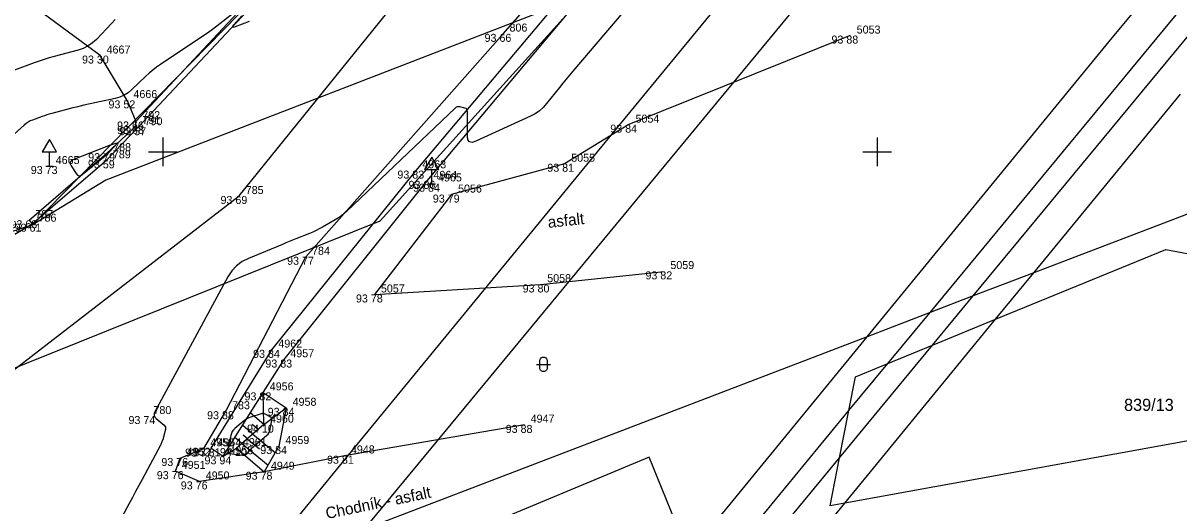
# Model space of a CAD drawing. Extents: x -711081 to -709338, y -1025122 to -1024092.
# Drawn here: x -709804.89 to -709764.45, y -1024537.41 to -1024520.49 of the extents above; entities that cross this region are included whole.
import ezdxf

# ---------------------------------------------------------------- set-up
doc = ezdxf.new("R2010")
doc.units = 0
for name, color, linetype in [('Ex_Major Contours', 7, 'Continuous'), ('Ex_Minor Contours', 7, 'Continuous'), ('Z_body', 7, 'Continuous'), ('Z_body_cisla', 7, 'Continuous'), ('Z_body_vysky_redukovane', 7, 'Continuous'), ('Z_cesta', 7, 'Continuous'), ('Z_dopravni_znacky', 7, 'Continuous'), ('Z_hektometricka_sit', 7, 'Continuous'), ('Z_hrany_paty', 7, 'Continuous'), ('Z_katastr_cisla_pozemkova', 7, 'Continuous'), ('Z_katastr_hranice', 7, 'Continuous'), ('Z_katastr_vnitrni_kresba', 7, 'Continuous'), ('Z_komunikace', 7, 'Continuous'), ('Z_komunikace_osa', 7, 'Continuous'), ('Z_obruba', 7, 'Continuous'), ('Z_popisy', 7, 'Continuous'), ('Z_rozhranni', 7, 'Continuous'), ('Z_svodidlo_betonove', 7, 'Continuous'), ('Z_technicke_srafy', 7, 'Continuous'), ('Z_znaky_kultur', 7, 'Continuous')]:
    doc.layers.add(name, color=color, linetype=linetype)

# ---------------------------------------------------------------- blocks, each defined once
blk = doc.blocks.new('POINT_DISPLAY')
blk.add_line((0, 0), (0, 0))
blk = doc.blocks.new('Z527')
for p, q in [((0, 0.93), (-0.25, 0.5)), ((0.25, 0.5), (0, 0.93)), ((-0.25, 0.5), (0.25, 0.5)), ((0, 0), (0, 0.5)), ((-0.13, 0), (0.13, 0))]:
    blk.add_line(p, q)
blk = doc.blocks.new('Z316')
for p, q in [((-0.25, 0), (0.25, 0)), ((-0.13, 0.15), (-0.1, 0.2)), ((-0.13, -0.15), (-0.13, 0.15)), ((-0.1, 0.2), (-0.08, 0.23)), ((-0.08, 0.23), (-0.03, 0.25)), ((-0.03, 0.25), (0.03, 0.25)), ((0.03, 0.25), (0.08, 0.23)), ((0.08, 0.23), (0.1, 0.2)), ((0.1, 0.2), (0.13, 0.15)), ((0.13, 0.15), (0.13, -0.15)), ((-0.1, -0.2), (-0.13, -0.15)), ((-0.08, -0.23), (-0.1, -0.2)), ((-0.03, -0.25), (-0.08, -0.23)), ((0.03, -0.25), (-0.03, -0.25)), ((0.08, -0.23), (0.03, -0.25)), ((0.1, -0.2), (0.08, -0.23)), ((0.13, -0.15), (0.1, -0.2))]:
    blk.add_line(p, q)

msp = doc.modelspace()

# ---------------------------------------------------------------- linework, layer by layer
at = {"layer": 'Ex_Major Contours'}
msp.add_lwpolyline([(-709797.721, -1024535.362), (-709797.724, -1024535.384), (-709797.724, -1024535.406), (-709797.724, -1024535.428), (-709797.717, -1024535.517), (-709797.713, -1024535.537), (-709797.704, -1024535.552), (-709797.689, -1024535.562), (-709797.67, -1024535.567), (-709797.214, -1024535.627), (-709797.167, -1024535.628), (-709797.124, -1024535.618), (-709797.086, -1024535.598), (-709797.05, -1024535.568), (-709796.917, -1024535.425), (-709796.884, -1024535.389), (-709796.849, -1024535.355), (-709796.813, -1024535.322), (-709796.777, -1024535.289), (-709796.366, -1024534.934), (-709796.32, -1024534.889), (-709796.285, -1024534.838), (-709796.258, -1024534.781), (-709796.241, -1024534.72), (-709796.183, -1024534.421), (-709796.181, -1024534.38), (-709796.19, -1024534.344), (-709796.211, -1024534.314), (-709796.244, -1024534.289), (-709796.399, -1024534.201), (-709796.439, -1024534.183), (-709796.479, -1024534.174), (-709796.52, -1024534.174), (-709796.562, -1024534.184), (-709796.925, -1024534.299), (-709796.998, -1024534.326), (-709797.067, -1024534.36), (-709797.132, -1024534.401), (-709797.193, -1024534.449), (-709797.478, -1024534.695), (-709797.53, -1024534.747), (-709797.572, -1024534.806), (-709797.604, -1024534.87), (-709797.626, -1024534.941), (-709797.717, -1024535.34)], close=True, dxfattribs=at)
at = {"layer": 'Ex_Minor Contours'}
for points in [[(-709782.085, -1024517.973), (-709785.654, -1024522.182), (-709785.772, -1024522.321), (-709785.888, -1024522.462), (-709786.003, -1024522.603), (-709786.118, -1024522.745), (-709786.573, -1024523.315), (-709786.693, -1024523.449), (-709786.826, -1024523.567), (-709786.972, -1024523.668), (-709787.131, -1024523.752), (-709789.054, -1024524.635), (-709789.18, -1024524.673), (-709789.271, -1024524.655), (-709789.325, -1024524.58), (-709789.342, -1024524.45), (-709789.34, -1024523.589), (-709789.346, -1024523.546), (-709789.363, -1024523.513), (-709789.391, -1024523.488), (-709789.431, -1024523.473), (-709789.614, -1024523.428), (-709789.658, -1024523.422), (-709789.699, -1024523.428), (-709789.737, -1024523.444), (-709789.773, -1024523.471), (-709793.558, -1024527.082), (-709793.653, -1024527.168), (-709793.753, -1024527.248), (-709793.858, -1024527.321), (-709793.967, -1024527.388), (-709794.416, -1024527.645), (-709794.527, -1024527.706), (-709794.64, -1024527.764), (-709794.756, -1024527.817), (-709794.873, -1024527.866), (-709795.346, -1024528.054), (-709795.464, -1024528.101), (-709795.582, -1024528.148), (-709795.7, -1024528.196), (-709795.818, -1024528.245), (-709797.004, -1024528.735), (-709797.227, -1024528.849), (-709797.421, -1024528.995), (-709797.586, -1024529.173), (-709797.722, -1024529.382), (-709800.281, -1024534.114), (-709800.306, -1024534.179), (-709800.307, -1024534.239), (-709800.284, -1024534.295), (-709800.238, -1024534.346), (-709799.96, -1024534.581), (-709799.931, -1024534.612), (-709799.913, -1024534.647), (-709799.906, -1024534.686), (-709799.911, -1024534.729), (-709799.961, -1024534.936), (-709799.968, -1024534.965), (-709799.976, -1024534.995), (-709799.985, -1024535.024), (-709799.995, -1024535.053), (-709800.035, -1024535.168), (-709800.046, -1024535.196), (-709800.057, -1024535.224), (-709800.07, -1024535.252), (-709800.084, -1024535.279), (-709800.728, -1024536.485), (-709800.84, -1024536.695), (-709800.953, -1024536.905), (-709801.065, -1024537.115), (-709801.177, -1024537.325), (-709802.637, -1024540.048)], [(-709797.157, -1024519.858), (-709798.003, -1024520.52), (-709798.158, -1024520.638), (-709798.314, -1024520.754), (-709798.473, -1024520.867), (-709798.634, -1024520.977), (-709800.08, -1024521.943), (-709800.218, -1024522.039), (-709800.351, -1024522.141), (-709800.48, -1024522.249), (-709800.604, -1024522.362), (-709801.092, -1024522.825), (-709801.22, -1024522.931), (-709801.358, -1024523.017), (-709801.506, -1024523.084), (-709801.665, -1024523.13), (-709802.761, -1024523.372), (-709802.892, -1024523.402), (-709803.023, -1024523.433), (-709803.153, -1024523.465), (-709803.282, -1024523.499), (-709803.889, -1024523.661), (-709803.974, -1024523.685), (-709804.059, -1024523.71), (-709804.143, -1024523.738), (-709804.226, -1024523.767), (-709804.558, -1024523.888), (-709804.639, -1024523.922), (-709804.716, -1024523.963), (-709804.788, -1024524.011), (-709804.856, -1024524.067), (-709806.483, -1024525.524)], [(-709796.977, -1024520.436), (-709797.466, -1024520.625), (-709797.529, -1024520.644), (-709797.558, -1024520.639), (-709797.553, -1024520.61), (-709797.513, -1024520.558), (-709797.236, -1024520.243)], [(-709801.665, -1024520.372), (-709801.797, -1024520.51), (-709802.327, -1024521.063), (-709802.466, -1024521.19), (-709802.619, -1024521.295), (-709802.784, -1024521.378), (-709802.962, -1024521.438), (-709803.801, -1024521.662), (-709803.979, -1024521.712), (-709804.155, -1024521.765), (-709804.331, -1024521.823), (-709804.505, -1024521.884), (-709805.198, -1024522.137)]]:
    msp.add_lwpolyline(points, dxfattribs=at)
msp.add_lwpolyline([(-709802.99, -1024525.82), (-709802.939, -1024525.844), (-709802.883, -1024525.838), (-709802.822, -1024525.801), (-709802.019, -1024525.146), (-709801.991, -1024525.123), (-709801.964, -1024525.098), (-709801.937, -1024525.073), (-709801.912, -1024525.046), (-709801.804, -1024524.93), (-709801.783, -1024524.907), (-709801.762, -1024524.885), (-709801.741, -1024524.862), (-709801.72, -1024524.84), (-709801.602, -1024524.715), (-709801.599, -1024524.71), (-709801.599, -1024524.707), (-709801.601, -1024524.706), (-709801.607, -1024524.706), (-709801.635, -1024524.707), (-709801.642, -1024524.708), (-709801.649, -1024524.709), (-709801.656, -1024524.711), (-709801.663, -1024524.713), (-709801.803, -1024524.759), (-709801.829, -1024524.768), (-709801.855, -1024524.777), (-709801.88, -1024524.786), (-709801.905, -1024524.796), (-709803.148, -1024525.289), (-709803.209, -1024525.325), (-709803.24, -1024525.37), (-709803.241, -1024525.424), (-709803.212, -1024525.489), (-709803.037, -1024525.766)], close=True, dxfattribs=at)
at = {"layer": 'Z_cesta'}
for p, q in [((-709802.2, -1024521.63), (-709804.24, -1024520.12)), ((-709801.25, -1024523.2), (-709802.2, -1024521.63)), ((-709801.25, -1024523.2), (-709800.95, -1024523.94))]:
    msp.add_line(p, q, dxfattribs=at)
at = {"layer": 'Z_hektometricka_sit'}
for p, q in [((-709800, -1024524.5), (-709800, -1024525.5)), ((-709775, -1024524.5), (-709775, -1024525.5)), ((-709800.5, -1024525), (-709799.5, -1024525)), ((-709775.5, -1024525), (-709774.5, -1024525))]:
    msp.add_line(p, q, dxfattribs=at)
at = {"layer": 'Z_hrany_paty'}
for p, q in [((-709796.49, -1024533.43), (-709795.68, -1024533.97)), ((-709796.47, -1024534.56), (-709796.49, -1024533.43)), ((-709796.47, -1024534.56), (-709795.68, -1024533.97)), ((-709795.68, -1024533.97), (-709795.94, -1024535.31)), ((-709796.47, -1024534.56), (-709797.42, -1024535.38)), ((-709797.89, -1024535.67), (-709797.42, -1024535.38)), ((-709797.42, -1024535.38), (-709796.45, -1024536.21)), ((-709795.94, -1024535.31), (-709796.45, -1024536.21))]:
    msp.add_line(p, q, dxfattribs=at)
at = {"layer": 'Z_katastr_hranice'}
for p, q in [((-709783.98, -1024524.02), (-709777.86, -1024516.55)), ((-709785.24, -1024519.5), (-709802, -1024526)), ((-709793.08, -1024535.12), (-709783.98, -1024524.02)), ((-709756.45, -1024524.23), (-709769.52, -1024529.24)), ((-709802, -1024526), (-709804.58, -1024527.57)), ((-709804.58, -1024527.57), (-709811.25, -1024529.69)), ((-709770.86, -1024530.87), (-709764.9, -1024528.42)), ((-709764.9, -1024528.42), (-709756.66, -1024530.01)), ((-709769.52, -1024529.24), (-709771.64, -1024530.05)), ((-709771.64, -1024530.05), (-709773.15, -1024530.63)), ((-709773.15, -1024530.63), (-709775.35, -1024531.48)), ((-709773.07, -1024531.78), (-709770.86, -1024530.87)), ((-709775.35, -1024531.48), (-709792.97, -1024538.24)), ((-709774.63, -1024532.42), (-709773.07, -1024531.78)), ((-709775.76, -1024532.89), (-709774.63, -1024532.42)), ((-709775.99, -1024534.07), (-709775.76, -1024532.89)), ((-709776.32, -1024535.72), (-709775.99, -1024534.07)), ((-709760.23, -1024534.42), (-709776.13, -1024537.31)), ((-709795.34, -1024537.87), (-709793.08, -1024535.12)), ((-709782.98, -1024535.7), (-709793.81, -1024540.21)), ((-709781.6, -1024539.11), (-709782.98, -1024535.7)), ((-709776.65, -1024537.4), (-709776.32, -1024535.72)), ((-709776.13, -1024537.31), (-709776.65, -1024537.4))]:
    msp.add_line(p, q, dxfattribs=at)
at = {"layer": 'Z_katastr_vnitrni_kresba'}
for p, q in [((-709766.78, -1024521.01), (-709758.92, -1024511.56)), ((-709773.15, -1024530.63), (-709758.42, -1024512.78)), ((-709771.64, -1024530.05), (-709758.24, -1024513.82)), ((-709773.68, -1024514.87), (-709792.97, -1024538.24)), ((-709804.58, -1024527.57), (-709794.45, -1024517.22)), ((-709792.4, -1024527.42), (-709785.24, -1024519.5)), ((-709775.35, -1024531.48), (-709766.78, -1024521.01)), ((-709769.52, -1024529.24), (-709764.39, -1024522.98)), ((-709829.33, -1024542.31), (-709792.4, -1024527.42)), ((-709770.86, -1024530.87), (-709769.52, -1024529.24)), ((-709773.07, -1024531.78), (-709771.64, -1024530.05)), ((-709774.63, -1024532.42), (-709773.15, -1024530.63)), ((-709776.13, -1024537.31), (-709770.86, -1024530.87)), ((-709781.6, -1024539.11), (-709775.35, -1024531.48)), ((-709776.32, -1024535.72), (-709773.07, -1024531.78)), ((-709775.99, -1024534.07), (-709774.63, -1024532.42)), ((-709781.12, -1024540.29), (-709775.99, -1024534.07)), ((-709780.78, -1024541.13), (-709776.32, -1024535.72)), ((-709780.28, -1024542.38), (-709776.13, -1024537.31))]:
    msp.add_line(p, q, dxfattribs=at)
at = {"layer": 'Z_komunikace'}
for p, q in [((-709788.09, -1024520.87), (-709780.35, -1024512.04)), ((-709800.87, -1024524.14), (-709796.7, -1024519.7)), ((-709795, -1024528.68), (-709788.09, -1024520.87)), ((-709801.97, -1024525.3), (-709800.87, -1024524.14)), ((-709804.58, -1024527.52), (-709801.97, -1024525.3)), ((-709810.36, -1024530.97), (-709804.58, -1024527.52)), ((-709797.8, -1024534.09), (-709795, -1024528.68)), ((-709798.57, -1024535.4), (-709797.8, -1024534.09)), ((-709787.35, -1024534.57), (-709793.65, -1024535.65)), ((-709799.4, -1024535.73), (-709798.57, -1024535.4)), ((-709799.56, -1024536.19), (-709799.4, -1024535.73)), ((-709793.65, -1024535.65), (-709796.45, -1024536.21)), ((-709798.72, -1024536.55), (-709799.56, -1024536.19)), ((-709796.45, -1024536.21), (-709798.72, -1024536.55))]:
    msp.add_line(p, q, dxfattribs=at)
at = {"layer": 'Z_komunikace_osa'}
for p, q in [((-709797.33, -1024526.55), (-709791, -1024518.69)), ((-709807.7, -1024534.56), (-709797.33, -1024526.55))]:
    msp.add_line(p, q, dxfattribs=at)
at = {"layer": 'Z_obruba'}
for p, q in [((-709800.95, -1024523.94), (-709796.84, -1024519.54)), ((-709801.96, -1024525.05), (-709800.95, -1024524.1)), ((-709800.95, -1024524.1), (-709800.95, -1024523.94)), ((-709804.68, -1024527.4), (-709801.96, -1024525.05)), ((-709804.68, -1024527.4), (-709804.58, -1024527.52))]:
    msp.add_line(p, q, dxfattribs=at)
at = {"layer": 'Z_rozhranni'}
for p, q in [((-709775.95, -1024520.93), (-709783.69, -1024524.05)), ((-709783.69, -1024524.05), (-709785.94, -1024525.42)), ((-709785.94, -1024525.42), (-709789.9, -1024526.5)), ((-709789.9, -1024526.5), (-709792.59, -1024530)), ((-709786.78, -1024529.65), (-709782.46, -1024529.19)), ((-709792.59, -1024530), (-709786.78, -1024529.65))]:
    msp.add_line(p, q, dxfattribs=at)
at = {"layer": 'Z_svodidlo_betonove'}
for p, q in [((-709791.14, -1024525.66), (-709780.82, -1024513.38)), ((-709790.75, -1024526.02), (-709780.45, -1024513.72)), ((-709796.19, -1024531.94), (-709791.14, -1024525.66)), ((-709795.76, -1024532.28), (-709790.75, -1024526.02)), ((-709798.31, -1024535.39), (-709796.19, -1024531.94)), ((-709796.49, -1024533.43), (-709795.76, -1024532.28)), ((-709797.89, -1024535.67), (-709796.49, -1024533.43)), ((-709798.31, -1024535.39), (-709797.89, -1024535.67))]:
    msp.add_line(p, q, dxfattribs=at)
at = {"layer": 'Z_technicke_srafy'}
for p, q in [((-709796.47, -1024534.56), (-709796.94, -1024534.15)), ((-709796.85, -1024534.89), (-709797.21, -1024534.58)), ((-709796.66, -1024534.73), (-709796.87, -1024534.55)), ((-709797.24, -1024535.22), (-709797.48, -1024535.01)), ((-709797.24, -1024535.22), (-709796.32, -1024535.98)), ((-709797.04, -1024535.06), (-709797.19, -1024534.93)), ((-709797.05, -1024535.06), (-709796.62, -1024535.41)), ((-709796.85, -1024534.89), (-709796.07, -1024535.54))]:
    msp.add_line(p, q, dxfattribs=at)

# ---------------------------------------------------------------- block references
at = {"layer": 'Z_body'}
for p in [(-709788.09, -1024520.87), (-709775.95, -1024520.93), (-709802.2, -1024521.63), (-709801.25, -1024523.2), (-709800.95, -1024523.94), (-709800.95, -1024524.1), (-709800.87, -1024524.14), (-709783.69, -1024524.05), (-709801.96, -1024525.05), (-709803.97, -1024525.5), (-709801.97, -1024525.3), (-709785.94, -1024525.42), (-709791.14, -1024525.66), (-709790.75, -1024526.02), (-709790.59, -1024526.12), (-709797.33, -1024526.55), (-709789.9, -1024526.5), (-709804.68, -1024527.4), (-709804.58, -1024527.52), (-709795, -1024528.68), (-709782.46, -1024529.19), (-709786.78, -1024529.65), (-709792.59, -1024530), (-709796.19, -1024531.94), (-709795.76, -1024532.28), (-709796.49, -1024533.43), (-709795.68, -1024533.97), (-709800.55, -1024534.26), (-709797.8, -1024534.09), (-709796.47, -1024534.56), (-709787.35, -1024534.57), (-709798.57, -1024535.4), (-709798.31, -1024535.39), (-709797.42, -1024535.38), (-709795.94, -1024535.31), (-709799.4, -1024535.73), (-709797.89, -1024535.67), (-709793.65, -1024535.65), (-709799.56, -1024536.19), (-709796.45, -1024536.21), (-709798.72, -1024536.55)]:
    msp.add_blockref('POINT_DISPLAY', p, dxfattribs=at)
at = {"layer": 'Z_dopravni_znacky'}
for p in [(-709803.97, -1024525.5), (-709790.59, -1024526.12)]:
    msp.add_blockref('Z527', p, dxfattribs=at)
at = {"layer": 'Z_znaky_kultur'}
msp.add_blockref('Z316', (-709786.68, -1024532.45), dxfattribs=at)

# ---------------------------------------------------------------- texts
at = {"layer": 'Z_body_cisla'}
for s, p in [('806', (-709787.87, -1024520.79)), ('5053', (-709775.72, -1024520.86)), ('4667', (-709801.97, -1024521.56)), ('4666', (-709801.03, -1024523.12)), ('792', (-709800.72, -1024523.86)), ('791', (-709800.72, -1024524.03)), ('790', (-709800.64, -1024524.07)), ('5054', (-709783.46, -1024523.98)), ('788', (-709801.74, -1024524.98)), ('789', (-709801.75, -1024525.23)), ('5055', (-709785.71, -1024525.35)), ('4665', (-709803.75, -1024525.43)), ('4963', (-709790.92, -1024525.58)), ('4964', (-709790.53, -1024525.95)), ('4965', (-709790.37, -1024526.04)), ('785', (-709797.1, -1024526.48)), ('5056', (-709789.67, -1024526.43)), ('787', (-709804.46, -1024527.32)), ('786', (-709804.35, -1024527.45)), ('784', (-709794.78, -1024528.61)), ('5059', (-709782.24, -1024529.11)), ('5058', (-709786.55, -1024529.57)), ('5057', (-709792.37, -1024529.93)), ('4962', (-709795.96, -1024531.86)), ('4957', (-709795.54, -1024532.2)), ('4956', (-709796.26, -1024533.36)), ('780', (-709800.33, -1024534.19)), ('783', (-709797.58, -1024534.02)), ('4958', (-709795.46, -1024533.9)), ('4960', (-709796.25, -1024534.49)), ('4947', (-709787.13, -1024534.49)), ('4953', (-709798.34, -1024535.32)), ('4954', (-709798.09, -1024535.32)), ('4961', (-709797.2, -1024535.31)), ('4959', (-709795.71, -1024535.24)), ('4952', (-709799.17, -1024535.65)), ('4955', (-709797.67, -1024535.6)), ('4948', (-709793.42, -1024535.57)), ('4951', (-709799.34, -1024536.11)), ('4949', (-709796.22, -1024536.14)), ('4950', (-709798.5, -1024536.48))]:
    msp.add_text(s, height=0.28, dxfattribs=at).set_placement(p)
at = {"layer": 'Z_body_vysky_redukovane'}
for s, p in [('93 66', (-709788.743, -1024521.15)), ('93 88', (-709776.603, -1024521.21)), ('93 30', (-709802.83, -1024521.91)), ('93 52', (-709801.903, -1024523.48)), ('93 66', (-709801.603, -1024524.22)), ('93 68', (-709801.603, -1024524.38)), ('93 57', (-709801.523, -1024524.42)), ('93 84', (-709784.343, -1024524.33)), ('93 79', (-709802.613, -1024525.33)), ('93 73', (-709804.623, -1024525.78)), ('93 59', (-709802.623, -1024525.58)), ('93 81', (-709786.547, -1024525.7)), ('93 83', (-709791.793, -1024525.94)), ('93 86', (-709791.403, -1024526.3)), ('93 84', (-709791.243, -1024526.4)), ('93 69', (-709797.983, -1024526.83)), ('93 79', (-709790.553, -1024526.78)), ('93 68', (-709805.333, -1024527.68)), ('93 61', (-709805.187, -1024527.8)), ('93 77', (-709795.653, -1024528.96)), ('93 82', (-709783.113, -1024529.47)), ('93 80', (-709787.41, -1024529.93)), ('93 78', (-709793.243, -1024530.28)), ('93 84', (-709796.843, -1024532.22)), ('93 83', (-709796.413, -1024532.56)), ('93 82', (-709797.143, -1024533.71)), ('93 84', (-709796.333, -1024534.25)), ('93 74', (-709801.203, -1024534.54)), ('93 88', (-709798.453, -1024534.37)), ('94 10', (-709797.053, -1024534.84)), ('93 88', (-709788.003, -1024534.85)), ('93 77', (-709799.223, -1024535.68)), ('93 81', (-709798.917, -1024535.67)), ('94 10', (-709798.003, -1024535.66)), ('93 84', (-709796.593, -1024535.59)), ('93 76', (-709800.053, -1024536.01)), ('93 94', (-709798.543, -1024535.95)), ('93 81', (-709794.257, -1024535.93)), ('93 76', (-709800.213, -1024536.47)), ('93 78', (-709797.103, -1024536.49)), ('93 76', (-709799.373, -1024536.83))]:
    msp.add_text(s, height=0.28, dxfattribs=at).set_placement(p)
at = {"layer": 'Z_katastr_cisla_pozemkova'}
msp.add_text('839/13', height=0.425, dxfattribs=at).set_placement((-709766.364, -1024534.08))
at = {"layer": 'Z_popisy'}
for s, rotation, p in [('asfalt', 6.3, (-709786.51, -1024527.67)), ('Chodník - asfalt', 11.7, (-709794.26, -1024537.87))]:
    msp.add_text(s, height=0.4, rotation=rotation, dxfattribs=at).set_placement(p)

doc.saveas('drawing.dxf')
